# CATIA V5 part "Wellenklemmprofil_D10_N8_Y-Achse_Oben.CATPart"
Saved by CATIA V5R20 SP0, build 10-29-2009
Part number: Wellenklemmprofil_D10_N8_Y-Achse_Oben
Bounding box of the stored display mesh (mm): x 0 to 668, y -9 to 9, z -12 to 15
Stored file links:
  C:\Users\Andi\Desktop\Plasma\Wellenklemmprofil_D10_N8_Y-Achse_Oben.CATPart
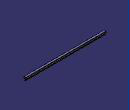
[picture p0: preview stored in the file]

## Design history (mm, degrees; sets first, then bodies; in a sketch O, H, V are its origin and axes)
Body1 (main body)
  Sketch1 on yz-plane, origin (0, 0, 0), H (0, 1, 0), V (0, 0, 1)
    line L1 (-9, 10) -> (-9, 0)
    point P2 (-9, 0)
    line L2 (-9, 0) -> (-4, 0)
    line L3 (-4, 0) -> (-4, -12)
    line L4 (-4, -12) -> (4, -12)
    line L5 (4, -12) -> (4, 0)
    point P6 (4, 0)
    line L6 (4, 0) -> (9, 0)
    line L7 (9, 0) -> (9, 10)
    line L8 (9, 10) -> (7.0993, 10)
    line L9 (-9, 10) -> (-7.0993, 10)
    arc A1 centre (0, 8) radius 7 from (-6.8075, 9.6301) to (6.8075, 9.6301) ccw
    point P9 (0, 8)
    arc A2 centre (-7.0993, 9.7) radius 0.3 from (-6.8075, 9.6301) to (-7.0993, 10) ccw
    arc A3 centre (7.0993, 9.7) radius 0.3 from (6.8075, 9.6301) to (7.0993, 10) cw
    radius A1 = 7
    distance L6 L8 = 10
    distance L7 L1 = 18
    radius A2 = 0.3
    radius A3 = 0.3 {= Sketch1.radius(A2)}
    distance P9 L6 = 8
    distance L8 L4 = 22
    distance L5 L3 = 8
    coincidence: P2 H, P6 H, P9 V, L9 L8
    vertical: L1 V, L3 V, L5 V, L7 V
    horizontal: L2 H, L4 H, L6 H, L8 H, L9 H
    symmetry: L7 L1 V, L3 L5 V
    tangency: A2 A1, A2 L9, A3 A1, A3 L8
  Pad1: profile Sketch1, direction (1, 0, 0), length 668
  Fillet1: radius 0.3, on edge [face of Pad1 from Sketch1.L8 | face of Pad1 from Sketch1.L7]; edge [face of Pad1 from Sketch1.L1 | face of Pad1 from Sketch1.L9]
Body2
  Sketch2 on yz-plane, origin (0, 0, 0), H (0, 1, 0), V (0, 0, 1)
    circle A1 centre (0, 8) radius 7
    reference projected arc E1 centre (0, 8) radius 7 from (-6.8182, 9.5849) to (6.8182, 9.5849) ccw from edge [face of Pad1 from Sketch1.A1 | end face of Pad1]
    coincidence: A1 E1
  Pad2: profile Sketch2, direction (1, 0, 0), length 668 {= Pad1.FirstLimit.Length}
